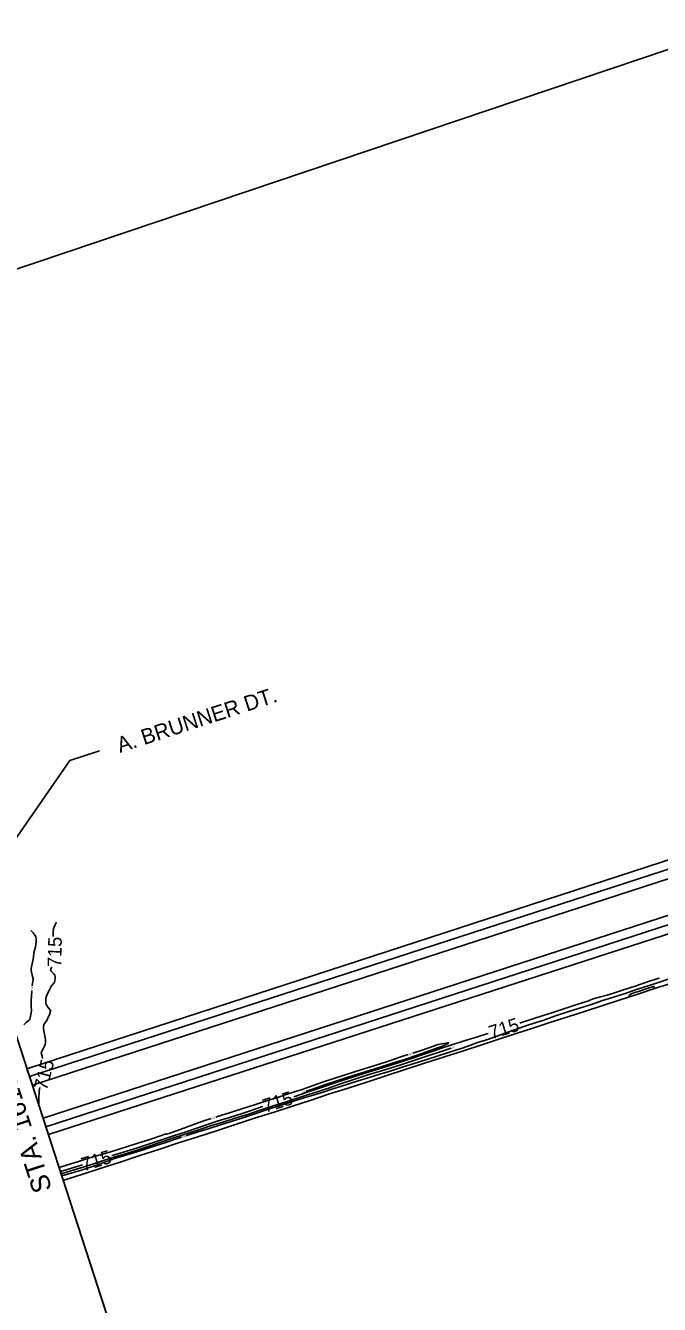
# Model space of a CAD drawing. Extents: x -468556195 to 3353078, y -306091294 to 1252632.
# Drawn here: x 1827114 to 1828648, y 532464 to 535561 of the extents above; entities that cross this region are included whole.
import ezdxf

# ---------------------------------------------------------------- set-up
doc = ezdxf.new("R2010")
doc.units = 0
for name, color, linetype in [('Default', 7, 'Continuous'), ('DT_X_Contour_Minor', 7, 'Continuous'), ('DT_X_Terrain_Ground_Line', 7, 'Continuous'), ('Level 14', 7, 'Continuous'), ('Level 19', 7, 'Continuous'), ('Level 40', 7, 'Continuous'), ('SC_Scratch1', 7, 'Continuous'), ('SC_Shading3', 7, 'Continuous')]:
    doc.layers.add(name, color=color, linetype=linetype)

msp = doc.modelspace()

# ---------------------------------------------------------------- linework, layer by layer
at = {"layer": 'Default'}
for points in [[(1827117.1, 533034.5), (1827123.3, 533015.5), (1834732.4, 535485.8), (1834724, 535511.6)], [(1827162.8, 532893.7), (1827168.8, 532875.3), (1833162.6, 534815.3), (1833154.9, 534839.7)]]:
    msp.add_lwpolyline(points, close=True, dxfattribs=at)
at = {"layer": 'DT_X_Contour_Minor'}
for points in [[(1827187.9, 533389.3), (1827187.3, 533386.7), (1827185.5, 533382.7), (1827181.8, 533375.9), (1827181, 533373.1), (1827180.7, 533366.8), (1827180.5, 533356.4), (1827180.6, 533354.8)], [(1827130, 533235.1), (1827130.6, 533242.1), (1827131.8, 533250), (1827131.7, 533252), (1827130.4, 533258.1), (1827127.3, 533272.2), (1827127, 533275.1), (1827127.3, 533277.4), (1827130.5, 533292.3), (1827132.6, 533305.1), (1827134, 533315.1), (1827137.7, 533329.8), (1827139.3, 533342.3), (1827139.6, 533346.2), (1827139.4, 533349.9), (1827138.5, 533353.5), (1827136.9, 533357.1), (1827134.7, 533360.5), (1827131.9, 533363.8), (1827126.5, 533369.4)], [(1827177.1, 533280.6), (1827174.1, 533275.2), (1827174.1, 533274.3), (1827174.5, 533272.8), (1827175.3, 533271.5), (1827176.8, 533269.7), (1827182.3, 533264.6), (1827184.6, 533261.3), (1827185.6, 533257.8), (1827185.7, 533254.1), (1827184.5, 533247.4), (1827183.6, 533244.6), (1827182.2, 533241.9), (1827178, 533236.8), (1827176, 533234.4), (1827174.6, 533232), (1827170.9, 533223.8), (1827167.8, 533218.4), (1827166, 533214.6), (1827164.3, 533210.2), (1827163, 533205.4), (1827162.3, 533200.6), (1827162.3, 533196.3), (1827163.1, 533192.1), (1827164.9, 533188), (1827167.6, 533183.8), (1827174.3, 533175.5), (1827174.4, 533173.8), (1827171.4, 533165.5), (1827168.7, 533159.1), (1827165.7, 533153.1), (1827159.9, 533145.3), (1827158.1, 533141.7), (1827157.3, 533136.9), (1827157.4, 533131.6), (1827158.7, 533122), (1827161, 533109.6), (1827161.5, 533105.1), (1827161.8, 533100.7), (1827161.5, 533096.7), (1827160.8, 533092.9), (1827159.3, 533088.9), (1827157.2, 533084.6), (1827152, 533075.1), (1827151.8, 533073.1), (1827153.6, 533064.7), (1827154.8, 533059.4)], [(1827502.6, 532872.2), (1827506.6, 532873.5), (1827534.1, 532882.5), (1827557.8, 532889.9), (1827585.4, 532898.7), (1827608.8, 532906.2), (1827642, 532916.8), (1827669, 532925.7), (1827699.6, 532935.9), (1827726.9, 532944.8), (1827755.2, 532953.9), (1827787.4, 532964.1), (1827810, 532970.8), (1827834.1, 532978.2), (1827857.8, 532986), (1827873.9, 532991.1), (1827896.2, 532997.9), (1827918.9, 533005.2), (1827945.9, 533013.5), (1827971.2, 533021.2), (1827996.3, 533028.8), (1828028.3, 533038.9), (1828054.5, 533047.3), (1828083, 533056.5), (1828112.4, 533065.7), (1828140.2, 533074.6), (1828171.1, 533084.7), (1828193.1, 533092.6), (1828208.1, 533097.7), (1828227.2, 533104), (1828253.3, 533113), (1828274.1, 533120.3), (1828304.6, 533131.2), (1828322.9, 533137.6), (1828352.5, 533147.1), (1828366.1, 533151.7), (1828396.9, 533162.6), (1828426.6, 533172.2), (1828454.7, 533181.1), (1828486.2, 533191.3), (1828508, 533198.7), (1828537.4, 533208.2), (1828567.9, 533217.8), (1828595, 533226.9), (1828623.6, 533236.4), (1828648.2, 533244.4), (1828669.9, 533251.3)], [(1828310.5, 533144.9), (1828311.8, 533145.4), (1828341.8, 533155.3), (1828366.9, 533163.2), (1828388.2, 533170.3), (1828411.9, 533178.1), (1828439.1, 533186.9), (1828466.2, 533195.6), (1828477.4, 533199.3), (1828480.1, 533200.5), (1828483.6, 533202.6), (1828488, 533204.1), (1828505.7, 533208.6), (1828521.9, 533212.6), (1828534.6, 533216.6), (1828561.8, 533225.7), (1828589.5, 533234.8), (1828619.8, 533244.9), (1828644.6, 533253), (1828648.3, 533254.2)], [(1827109.5, 533141.2), (1827115.2, 533146.4), (1827119.6, 533150.4), (1827123.4, 533153.3), (1827124.3, 533154.8), (1827125, 533157.5), (1827126.5, 533166), (1827127.6, 533175), (1827127.2, 533185.9), (1827127, 533199.9), (1827129, 533223.1)], [(1828575.4, 533207.6), (1828574.8, 533209.8), (1828575, 533211.8), (1828576.7, 533213.8), (1828580.2, 533215.8), (1828588.6, 533219), (1828599.8, 533222.7), (1828618.9, 533228.9), (1828634.4, 533233.8), (1828635.2, 533233.9), (1828635.8, 533232.2), (1828636.4, 533230), (1828636.5, 533227.4)], [(1827763.2, 532966.9), (1827795.1, 532977.5), (1827827.5, 532988.5), (1827851.2, 532996.3), (1827880.1, 533005.9), (1827906, 533014.3), (1827935, 533023.6), (1827967.4, 533033.5), (1827993, 533041.6), (1828023.2, 533051.3), (1828050.4, 533060.1), (1828071.6, 533067.2), (1828098, 533076.5), (1828118.6, 533083.4), (1828145.6, 533092.2), (1828175.7, 533102), (1828207.5, 533111.7), (1828230.8, 533119.1), (1828234, 533120.1)], [(1828051.6, 533072.5), (1828053.7, 533073.2), (1828071.2, 533079), (1828101.3, 533089.3), (1828112.5, 533092.9), (1828120.5, 533094.7), (1828132.6, 533096.8), (1828136.4, 533097.3), (1828138.2, 533097.1), (1828136.9, 533096), (1828129.3, 533092.2), (1828119.3, 533087.7), (1828111.1, 533084.9), (1828093.3, 533078.5), (1828061.8, 533067.2), (1828033.4, 533058.1), (1828006.7, 533049.5), (1827974.6, 533039.1), (1827948.7, 533031), (1827917.6, 533021.4), (1827891.4, 533013.1), (1827866.9, 533005.1), (1827837.4, 532995.4), (1827822.1, 532990.2), (1827798.5, 532981.9), (1827792.6, 532979.9)], [(1828144.3, 533084.4), (1828117.6, 533075.3), (1828087.6, 533065.5), (1828061, 533056.6), (1828029.4, 533046.2), (1828001.8, 533037.4), (1827975.1, 533029.1), (1827942.5, 533019.5), (1827930.6, 533015.8), (1827903.6, 533006.7), (1827876.3, 532997.6), (1827845, 532987), (1827827.8, 532981.3), (1827798.8, 532972.2), (1827771.5, 532963.3), (1827741.8, 532953.6), (1827713.4, 532944.6), (1827682, 532934.4), (1827653.3, 532924.9), (1827623.3, 532915.3), (1827591.3, 532905.5), (1827561.3, 532895.9), (1827526, 532884.3), (1827497.5, 532874.9), (1827468.1, 532865.3), (1827438.7, 532855.7), (1827410.6, 532846.4), (1827378.8, 532836.1), (1827352, 532828), (1827329.6, 532821.2), (1827302.4, 532812.1), (1827280.5, 532804.9), (1827252.7, 532796.4), (1827223.1, 532787.3), (1827199.7, 532780.1)], [(1827574.7, 532917.5), (1827581.1, 532919.5), (1827607.7, 532927.8), (1827640, 532937.9), (1827667.6, 532947.3), (1827694.3, 532956.2), (1827726.2, 532966.1), (1827752.2, 532974.4), (1827783, 532984.5), (1827809.9, 532993.9), (1827835.4, 533002.7), (1827864.5, 533012.5), (1827880.5, 533017.7), (1827909.9, 533027.1), (1827935.7, 533035.1), (1827967.2, 533044.9), (1827994.7, 533054), (1828022.3, 533063.1), (1828040.2, 533068.8)], [(1827148.4, 532989.1), (1827147.6, 532985.6), (1827146.5, 532978.3), (1827145.7, 532962.8), (1827146.1, 532949.5), (1827145.9, 532946.7), (1827145.8, 532946.1)], [(1827322.9, 532824.1), (1827329.1, 532826.1), (1827361, 532835.7), (1827386.8, 532843.8), (1827415.8, 532853.3), (1827442.9, 532862.5), (1827471.5, 532871.9), (1827502.8, 532882.1), (1827528.5, 532891), (1827551.4, 532898.9), (1827577.3, 532907.2), (1827607.6, 532916.8), (1827635.8, 532925.6), (1827657.3, 532932.6), (1827684.8, 532941.9), (1827688, 532942.9)], [(1827194.8, 532795.3), (1827212.9, 532801.2), (1827241.4, 532810.1), (1827268.8, 532818.6), (1827300.6, 532828), (1827327, 532835.8), (1827358.4, 532845.3), (1827385.7, 532854), (1827411.9, 532862.6), (1827442.4, 532873.1), (1827450.7, 532875.8), (1827455.2, 532876.1), (1827460.5, 532877.6), (1827479.4, 532884.4), (1827503.6, 532893.3), (1827533.9, 532904.1), (1827550.2, 532909.6), (1827563.3, 532913.8)], [(1827201.3, 532775.2), (1827226.7, 532782.3), (1827249.4, 532789.1), (1827266, 532794.5), (1827289.6, 532802.9), (1827319, 532813.5), (1827331.4, 532817.7), (1827356.4, 532825), (1827372.9, 532829.9), (1827395.6, 532837.4), (1827427.2, 532847.7), (1827453.1, 532856.1), (1827484.1, 532866.2), (1827491.2, 532868.5)], [(1827198, 532785.4), (1827214, 532790.5), (1827240.9, 532798.9), (1827251.1, 532802)]]:
    msp.add_lwpolyline(points, dxfattribs=at)
at = {"layer": 'DT_X_Terrain_Ground_Line'}
msp.add_line((1827446.8, 532019.1), (1826839.3, 533890.1), dxfattribs=at)
at = {"layer": 'Level 14'}
for points in [[(1828680.5, 533242.9), (1828636.2, 533228.6), (1828593.4, 533214.4), (1828550.6, 533200.6), (1828508.6, 533186.9)], [(1828508.6, 533186.9), (1828466.6, 533173.2), (1828426.3, 533160.3), (1828383.1, 533146.2), (1828339.5, 533132), (1828304, 533120.5), (1828259.8, 533105.9), (1828218.6, 533092.8), (1828174.3, 533078.2), (1828127.9, 533063.2), (1828079.7, 533047.8), (1828032.9, 533032.4), (1827985.7, 533017), (1827939.9, 533002.3), (1827895.1, 532987.8), (1827849.8, 532973.4), (1827805, 532958.7), (1827760, 532944.2), (1827715.2, 532929.7), (1827668.1, 532914.5), (1827621.6, 532899.3), (1827578, 532885.3), (1827530.7, 532870), (1827484.3, 532854.8), (1827436.6, 532839.3), (1827390.5, 532824.2), (1827342.6, 532808.6), (1827296.3, 532793.5), (1827249.9, 532778.5), (1827206.4, 532764.5), (1827204.8, 532764)]]:
    msp.add_lwpolyline(points, dxfattribs=at)
at = {"layer": 'Level 40'}
msp.add_lwpolyline([(1827070.7, 533564.1), (1827221.2, 533781.2), (1827292.5, 533804.4)], dxfattribs=at)
at = {"layer": 'SC_Scratch1'}
msp.add_lwpolyline([(1826839.3, 533890.1), (1826769.8, 534863.1), (1833950.4, 537284.3), (1834448.3, 536360.7), (1835055.9, 534489.2), (1835128.1, 533209.3), (1827818.5, 531160.4), (1827446.8, 532019.1)], close=True, dxfattribs=at)
at = {"layer": 'SC_Shading3'}
for points in [[(1827130.1, 532994.6), (1827117.1, 533034.5), (1834724, 535511.6), (1834739.2, 535464.9)], [(1827156, 532914.7), (1827168.8, 532875.3), (1833162.6, 534815.3), (1833148.1, 534860)]]:
    msp.add_lwpolyline(points, close=True, dxfattribs=at)

# ---------------------------------------------------------------- texts
at = {"layer": 'DT_X_Terrain_Ground_Line'}
msp.add_text('MATCH LINE                  STA. 1610+00', height=46.8, rotation=107.9864, dxfattribs=at).set_placement((1827391.9, 532085))
at = {"layer": 'Level 19'}
for s, height, rotation, p in [('715', 33, 88.5965, (1827199.8, 533280.1)), ('716', 4, 85.0785, (1827131, 533223.6)), ('715', 33, 17.6127, (1828241.6, 533105.3)), ('714', 4, 17.8476, (1828041.5, 533067.1)), ('717', 4, 19.0623, (1828145.6, 533082.7)), ('715', 33, 75.1205, (1827164.8, 532980.4)), ('715', 33, 17.3205, (1827693.8, 532927.7)), ('714', 4, 18.6727, (1827782.6, 532974.4)), ('714', 4, 17.8935, (1827564.6, 532912.1)), ('718', 4, 18.0424, (1827492.5, 532866.9)), ('715', 33, 16.7705, (1827254.2, 532785.9))]:
    msp.add_text(s, height=height, rotation=rotation, dxfattribs=at).set_placement(p)
at = {"layer": 'Level 40'}
msp.add_text('A. BRUNNER DT.', height=37.5, rotation=17.9864, dxfattribs=at).set_placement((1827342.1, 533799.4))

doc.saveas('drawing.dxf')
